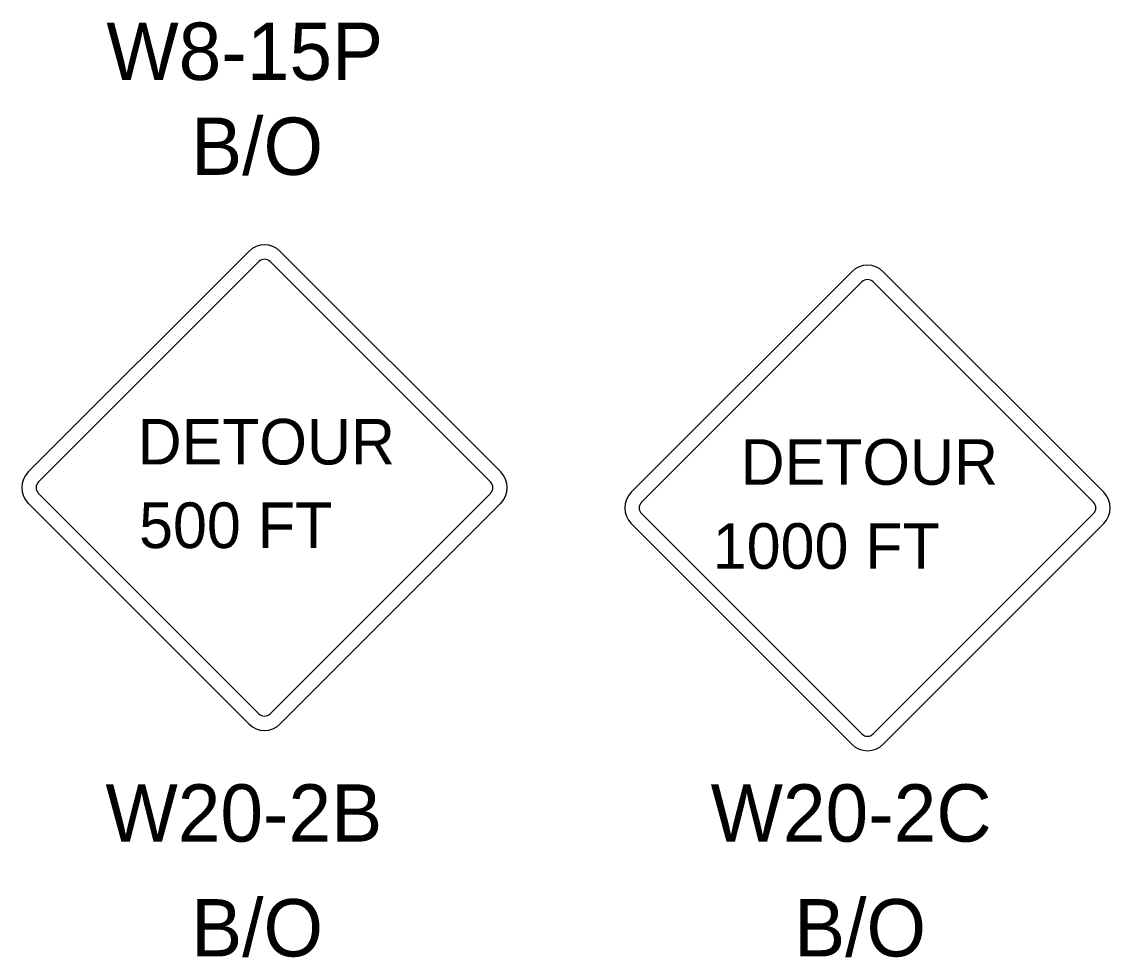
# Model space of a CAD drawing. Extents: x 10000 to 10794, y 10000 to 10499.
# Drawn here: x 10653.1 to 10719.6, y 10279.5 to 10336.6 of the extents above; entities that cross this region are included whole.
import ezdxf

# ---------------------------------------------------------------- set-up
doc = ezdxf.new("R2010")
doc.units = 0
for name, color, linetype in [('DSText', 7, 'Continuous'), ('DSTitle', 7, 'Continuous'), ('PlotBorder_dp', 7, 'Continuous')]:
    doc.layers.add(name, color=color, linetype=linetype)

msp = doc.modelspace()

# ---------------------------------------------------------------- linework, layer by layer
at = {"layer": 'DSText'}
for p, q in [((10653.511, 10309.134), (10666.987, 10322.608)), ((10668.901, 10322.608), (10682.376, 10309.134)), ((10690.343, 10307.894), (10703.819, 10321.369)), ((10705.734, 10321.369), (10719.208, 10307.894)), ((10666.987, 10293.743), (10653.511, 10307.219)), ((10682.376, 10307.219), (10668.901, 10293.743)), ((10703.819, 10292.505), (10690.343, 10305.979)), ((10719.208, 10305.979), (10705.734, 10292.505))]:
    msp.add_line(p, q, dxfattribs=at)
for centre, start, end in [((10667.943, 10321.646), 45, 135), ((10704.776, 10320.407), 45, 135), ((10654.474, 10308.177), 135, 225), ((10681.413, 10308.177), 315, 45), ((10691.306, 10306.938), 135, 225), ((10718.245, 10306.938), 315, 45), ((10667.947, 10294.705), 225, 315), ((10704.779, 10293.466), 225, 315)]:
    msp.add_arc(centre, 1.358, start, end, dxfattribs=at)
at = {"layer": 'DSTitle'}
for p, q in [((10654.137, 10308.524), (10667.596, 10321.982)), ((10668.292, 10321.982), (10681.75, 10308.524)), ((10690.969, 10307.285), (10704.428, 10320.743)), ((10705.125, 10320.743), (10718.582, 10307.285)), ((10667.596, 10294.37), (10654.137, 10307.828)), ((10681.75, 10307.828), (10668.292, 10294.37)), ((10704.428, 10293.131), (10690.969, 10306.589)), ((10718.582, 10306.589), (10705.125, 10293.131))]:
    msp.add_line(p, q, dxfattribs=at)
for centre, start, end in [((10667.943, 10321.637), 45, 135), ((10704.776, 10320.398), 45, 135), ((10654.482, 10308.177), 135, 225), ((10681.404, 10308.177), 315, 45), ((10691.315, 10306.938), 135, 225), ((10718.236, 10306.938), 315, 45), ((10667.943, 10294.716), 225, 315), ((10704.776, 10293.477), 225, 315)]:
    msp.add_arc(centre, 0.49, start, end, dxfattribs=at)

# ---------------------------------------------------------------- texts
at = {"layer": 'PlotBorder_dp'}
for s, height, p in [('W8-15P', 3.5, (10658.283, 10333.081)), ('B/O', 3.5, (10663.458, 10327.282)), ('DETOUR', 2.7855, (10660.189, 10309.591)), ('DETOUR', 2.7855, (10697.023, 10308.352)), ('500 FT', 2.7855, (10660.282, 10304.486)), ('1000 FT', 2.7855, (10695.324, 10303.218)), ('W20-2B', 3.5, (10658.229, 10286.554)), ('W20-2C', 3.5, (10695.193, 10286.554)), ('B/O', 3.5, (10663.458, 10279.543)), ('B/O', 3.5, (10700.291, 10279.543))]:
    msp.add_text(s, height=height, dxfattribs=at).set_placement(p)

doc.saveas('drawing.dxf')
